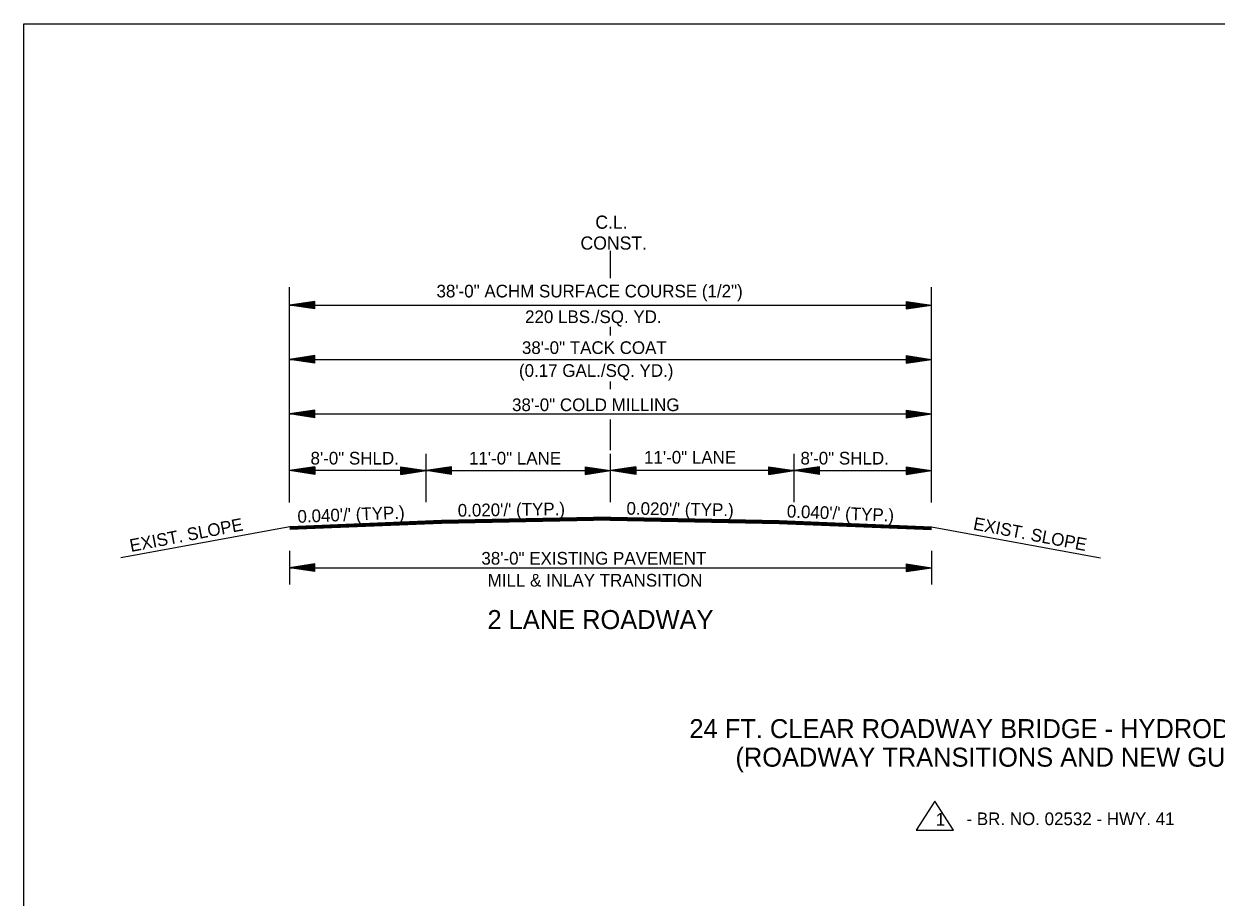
# Model space of a CAD drawing. Extents: x 544199 to 1930787, y -1968972 to 596640.
# Drawn here: x 544199 to 544905, y -1947820 to -1947303 of the extents above; entities that cross this region are included whole.
import ezdxf

# ---------------------------------------------------------------- set-up
doc = ezdxf.new("R2010")
doc.units = 0
for name, color, linetype in [('R_Border', 7, 'Continuous'), ('R_Draft', 7, 'Continuous'), ('R_No Plot', 7, 'Continuous')]:
    doc.layers.add(name, color=color, linetype=linetype)

msp = doc.modelspace()

# ---------------------------------------------------------------- linework, layer by layer
at = {"layer": 'R_Border'}
for p, q in [((544446.09, -1947597.4), (544356.44, -1947600.99)), ((544446.09, -1947597.7), (544356.44, -1947601.29)), ((544446.09, -1947598), (544356.44, -1947601.59)), ((544446.09, -1947598.3), (544356.44, -1947601.89)), ((544446.09, -1947598.6), (544356.44, -1947602.19)), ((544446.09, -1947598.9), (544356.44, -1947602.49)), ((544446.09, -1947599.07), (544356.44, -1947602.66)), ((544646.09, -1947597.4), (544736.09, -1947601)), ((544646.09, -1947597.7), (544736.09, -1947601.3)), ((544646.09, -1947598), (544736.09, -1947601.6)), ((544646.09, -1947598.3), (544736.09, -1947601.9)), ((544646.09, -1947598.6), (544736.09, -1947602.2)), ((544646.09, -1947598.9), (544736.09, -1947602.5)), ((544646.09, -1947599.07), (544736.09, -1947602.67)), ((544738.08, -1947763.37), (544727.04, -1947780.67)), ((544749.12, -1947780.67), (544738.08, -1947763.37)), ((544727.04, -1947780.67), (544749.12, -1947780.67))]:
    msp.add_line(p, q, dxfattribs=at)
at = {"layer": 'R_Draft'}
for p, q in [((544546.09, -1947453.82), (544546.09, -1947437.75)), ((544356.09, -1947586.62), (544356.09, -1947459.14)), ((544736.09, -1947586.62), (544736.09, -1947459.14)), ((544371.09, -1947467.62), (544356.09, -1947469.87)), ((544371.09, -1947468), (544358.59, -1947469.87)), ((544371.09, -1947468.38), (544361.17, -1947469.87)), ((544371.09, -1947468.75), (544363.67, -1947469.87)), ((544371.09, -1947469.14), (544366.21, -1947469.87)), ((544371.09, -1947469.52), (544368.72, -1947469.87)), ((544371.09, -1947472.12), (544371.09, -1947467.62)), ((544721.09, -1947467.62), (544736.09, -1947469.87)), ((544721.09, -1947467.62), (544721.09, -1947472.12)), ((544721.09, -1947468), (544733.58, -1947469.87)), ((544721.09, -1947468.38), (544731, -1947469.87)), ((544721.09, -1947468.75), (544728.51, -1947469.87)), ((544721.09, -1947469.14), (544725.96, -1947469.87)), ((544721.09, -1947469.52), (544723.46, -1947469.87)), ((544356.09, -1947469.87), (544736.09, -1947469.87)), ((544371.09, -1947472.12), (544356.09, -1947469.87)), ((544371.09, -1947471.75), (544358.59, -1947469.87)), ((544371.09, -1947471.36), (544361.17, -1947469.87)), ((544371.09, -1947470.99), (544363.67, -1947469.87)), ((544371.09, -1947470.6), (544366.21, -1947469.87)), ((544371.09, -1947470.22), (544368.72, -1947469.87)), ((544721.09, -1947472.12), (544736.09, -1947469.87)), ((544721.09, -1947470.61), (544725.96, -1947469.87)), ((544721.09, -1947471.36), (544731, -1947469.87)), ((544721.09, -1947471.75), (544733.58, -1947469.87)), ((544721.09, -1947470.99), (544728.51, -1947469.87)), ((544721.09, -1947470.22), (544723.46, -1947469.87)), ((544546.09, -1947487.76), (544546.09, -1947482.72)), ((544371.09, -1947499.77), (544356.09, -1947502.02)), ((544356.09, -1947502.02), (544736.09, -1947502.02)), ((544371.09, -1947504.27), (544356.09, -1947502.02)), ((544371.09, -1947500.14), (544358.59, -1947502.02)), ((544371.09, -1947503.89), (544358.59, -1947502.02)), ((544371.09, -1947500.53), (544361.17, -1947502.02)), ((544371.09, -1947503.51), (544361.17, -1947502.02)), ((544371.09, -1947500.9), (544363.67, -1947502.02)), ((544371.09, -1947503.14), (544363.67, -1947502.02)), ((544371.09, -1947501.28), (544366.21, -1947502.02)), ((544371.09, -1947502.75), (544366.21, -1947502.02)), ((544371.09, -1947501.67), (544368.72, -1947502.02)), ((544371.09, -1947502.37), (544368.72, -1947502.02)), ((544371.09, -1947504.27), (544371.09, -1947499.77)), ((544721.09, -1947499.77), (544736.09, -1947502.02)), ((544721.09, -1947499.77), (544721.09, -1947504.27)), ((544721.09, -1947500.14), (544733.58, -1947502.02)), ((544721.09, -1947500.53), (544731, -1947502.02)), ((544721.09, -1947500.9), (544728.51, -1947502.02)), ((544721.09, -1947501.29), (544725.96, -1947502.02)), ((544721.09, -1947501.67), (544723.46, -1947502.02)), ((544721.09, -1947504.27), (544736.09, -1947502.02)), ((544721.09, -1947502.75), (544725.96, -1947502.02)), ((544721.09, -1947503.51), (544731, -1947502.02)), ((544721.09, -1947503.89), (544733.58, -1947502.02)), ((544721.09, -1947503.14), (544728.51, -1947502.02)), ((544721.09, -1947502.37), (544723.46, -1947502.02)), ((544546.09, -1947519.61), (544546.09, -1947515.15)), ((544371.09, -1947532.01), (544356.09, -1947534.26)), ((544371.09, -1947532.38), (544358.59, -1947534.26)), ((544371.09, -1947532.76), (544361.17, -1947534.26)), ((544371.09, -1947533.14), (544363.67, -1947534.26)), ((544371.09, -1947536.51), (544371.09, -1947532.01)), ((544721.09, -1947532.01), (544736.09, -1947534.26)), ((544721.09, -1947532.01), (544721.09, -1947536.51)), ((544721.09, -1947532.38), (544733.58, -1947534.26)), ((544721.09, -1947532.76), (544731, -1947534.26)), ((544721.09, -1947533.14), (544728.51, -1947534.26)), ((544356.09, -1947534.26), (544736.09, -1947534.26)), ((544371.09, -1947536.51), (544356.09, -1947534.26)), ((544371.09, -1947536.13), (544358.59, -1947534.26)), ((544371.09, -1947535.75), (544361.17, -1947534.26)), ((544371.09, -1947535.37), (544363.67, -1947534.26)), ((544371.09, -1947533.52), (544366.21, -1947534.26)), ((544371.09, -1947534.98), (544366.21, -1947534.26)), ((544371.09, -1947533.9), (544368.72, -1947534.26)), ((544371.09, -1947534.61), (544368.72, -1947534.26)), ((544546.09, -1947555.78), (544546.09, -1947537.59)), ((544721.09, -1947533.53), (544725.96, -1947534.26)), ((544721.09, -1947533.9), (544723.46, -1947534.26)), ((544721.09, -1947536.51), (544736.09, -1947534.26)), ((544721.09, -1947534.99), (544725.96, -1947534.26)), ((544721.09, -1947535.75), (544731, -1947534.26)), ((544721.09, -1947536.13), (544733.58, -1947534.26)), ((544721.09, -1947535.37), (544728.51, -1947534.26)), ((544721.09, -1947534.61), (544723.46, -1947534.26)), ((544437.1, -1947586.45), (544437.1, -1947557.9)), ((544546.09, -1947586.45), (544546.09, -1947557.9)), ((544654.85, -1947586.45), (544654.85, -1947557.9)), ((544371.09, -1947565.54), (544356.09, -1947567.79)), ((544437.1, -1947567.79), (544356.09, -1947567.79)), ((544371.09, -1947570.04), (544356.09, -1947567.79)), ((544371.09, -1947565.92), (544358.59, -1947567.79)), ((544371.09, -1947569.67), (544358.59, -1947567.79)), ((544371.09, -1947566.3), (544361.17, -1947567.79)), ((544371.09, -1947569.29), (544361.17, -1947567.79)), ((544371.09, -1947566.68), (544363.67, -1947567.79)), ((544371.09, -1947568.91), (544363.67, -1947567.79)), ((544371.09, -1947567.07), (544366.21, -1947567.79)), ((544371.09, -1947568.53), (544366.21, -1947567.79)), ((544371.09, -1947567.44), (544368.72, -1947567.79)), ((544371.09, -1947568.15), (544368.72, -1947567.79)), ((544371.09, -1947565.54), (544371.09, -1947570.04)), ((544422.1, -1947565.54), (544437.1, -1947567.79)), ((544422.1, -1947570.04), (544422.1, -1947565.54)), ((544422.1, -1947565.92), (544434.59, -1947567.79)), ((544422.1, -1947566.3), (544432.01, -1947567.79)), ((544422.1, -1947566.68), (544429.52, -1947567.79)), ((544422.1, -1947567.06), (544426.97, -1947567.79)), ((544422.1, -1947567.44), (544424.47, -1947567.79)), ((544422.1, -1947570.04), (544437.1, -1947567.79)), ((544422.1, -1947568.52), (544426.97, -1947567.79)), ((544422.1, -1947569.29), (544432.01, -1947567.79)), ((544422.1, -1947569.67), (544434.59, -1947567.79)), ((544422.1, -1947568.91), (544429.52, -1947567.79)), ((544422.1, -1947568.15), (544424.47, -1947567.79)), ((544452.1, -1947565.54), (544437.1, -1947567.79)), ((544452.1, -1947570.04), (544437.1, -1947567.79)), ((544437.1, -1947567.79), (544546.09, -1947567.79)), ((544452.1, -1947565.92), (544439.6, -1947567.79)), ((544452.1, -1947569.67), (544439.6, -1947567.79)), ((544452.1, -1947566.3), (544442.18, -1947567.79)), ((544452.1, -1947569.29), (544442.18, -1947567.79)), ((544452.1, -1947566.68), (544444.68, -1947567.79)), ((544452.1, -1947568.91), (544444.68, -1947567.79)), ((544452.1, -1947567.06), (544447.22, -1947567.79)), ((544452.1, -1947568.52), (544447.22, -1947567.79)), ((544452.1, -1947567.44), (544449.73, -1947567.79)), ((544452.1, -1947568.15), (544449.73, -1947567.79)), ((544452.1, -1947570.04), (544452.1, -1947565.54)), ((544531.09, -1947565.54), (544546.09, -1947567.79)), ((544531.09, -1947565.54), (544531.09, -1947570.04)), ((544531.09, -1947565.92), (544543.58, -1947567.79)), ((544531.09, -1947566.3), (544541, -1947567.79)), ((544531.09, -1947566.68), (544538.51, -1947567.79)), ((544531.09, -1947567.07), (544535.96, -1947567.79)), ((544531.09, -1947567.44), (544533.46, -1947567.79)), ((544531.09, -1947570.04), (544546.09, -1947567.79)), ((544531.09, -1947568.53), (544535.96, -1947567.79)), ((544531.09, -1947569.29), (544541, -1947567.79)), ((544531.09, -1947569.67), (544543.58, -1947567.79)), ((544531.09, -1947568.91), (544538.51, -1947567.79)), ((544531.09, -1947568.15), (544533.46, -1947567.79)), ((544561.09, -1947565.54), (544546.09, -1947567.79)), ((544654.85, -1947567.79), (544546.09, -1947567.79)), ((544561.09, -1947570.04), (544546.09, -1947567.79)), ((544561.09, -1947565.92), (544548.59, -1947567.79)), ((544561.09, -1947569.67), (544548.59, -1947567.79)), ((544561.09, -1947566.3), (544551.17, -1947567.79)), ((544561.09, -1947569.29), (544551.17, -1947567.79)), ((544561.09, -1947566.68), (544553.67, -1947567.79)), ((544561.09, -1947568.91), (544553.67, -1947567.79)), ((544561.09, -1947567.07), (544556.21, -1947567.79)), ((544561.09, -1947568.53), (544556.21, -1947567.79)), ((544561.09, -1947567.44), (544558.72, -1947567.79)), ((544561.09, -1947568.15), (544558.72, -1947567.79)), ((544561.09, -1947565.54), (544561.09, -1947570.04)), ((544639.85, -1947565.54), (544654.85, -1947567.79)), ((544639.85, -1947570.04), (544639.85, -1947565.54)), ((544639.85, -1947565.92), (544652.34, -1947567.79)), ((544639.85, -1947566.3), (544649.76, -1947567.79)), ((544639.85, -1947566.68), (544647.26, -1947567.79)), ((544639.85, -1947567.06), (544644.72, -1947567.79)), ((544639.85, -1947567.44), (544642.22, -1947567.79)), ((544639.85, -1947570.04), (544654.85, -1947567.79)), ((544639.85, -1947568.52), (544644.72, -1947567.79)), ((544639.85, -1947569.29), (544649.76, -1947567.79)), ((544639.85, -1947569.67), (544652.34, -1947567.79)), ((544639.85, -1947568.91), (544647.26, -1947567.79)), ((544639.85, -1947568.15), (544642.22, -1947567.79)), ((544669.85, -1947565.54), (544654.85, -1947567.79)), ((544654.85, -1947567.79), (544736.09, -1947567.79)), ((544669.85, -1947570.04), (544654.85, -1947567.79)), ((544669.85, -1947565.92), (544657.35, -1947567.79)), ((544669.85, -1947569.67), (544657.35, -1947567.79)), ((544669.85, -1947566.3), (544659.93, -1947567.79)), ((544669.85, -1947569.29), (544659.93, -1947567.79)), ((544669.85, -1947566.68), (544662.43, -1947567.79)), ((544669.85, -1947568.91), (544662.43, -1947567.79)), ((544669.85, -1947567.06), (544664.97, -1947567.79)), ((544669.85, -1947568.52), (544664.97, -1947567.79)), ((544669.85, -1947567.44), (544667.48, -1947567.79)), ((544669.85, -1947568.15), (544667.48, -1947567.79)), ((544669.85, -1947570.04), (544669.85, -1947565.54)), ((544721.09, -1947565.54), (544736.09, -1947567.79)), ((544721.09, -1947565.54), (544721.09, -1947570.04)), ((544721.09, -1947565.92), (544733.58, -1947567.79)), ((544721.09, -1947566.3), (544731, -1947567.79)), ((544721.09, -1947566.68), (544728.51, -1947567.79)), ((544721.09, -1947567.07), (544725.96, -1947567.79)), ((544721.09, -1947567.44), (544723.46, -1947567.79)), ((544721.09, -1947570.04), (544736.09, -1947567.79)), ((544721.09, -1947568.53), (544725.96, -1947567.79)), ((544721.09, -1947569.29), (544731, -1947567.79)), ((544721.09, -1947569.67), (544733.58, -1947567.79)), ((544721.09, -1947568.91), (544728.51, -1947567.79)), ((544721.09, -1947568.15), (544723.46, -1947567.79)), ((544546.09, -1947595.4), (544446.09, -1947597.4)), ((544546.08, -1947595.7), (544446.09, -1947597.7)), ((544546.09, -1947596), (544446.09, -1947598)), ((544546.11, -1947596.3), (544446.09, -1947598.3)), ((544546.11, -1947596.6), (544446.09, -1947598.6)), ((544546.07, -1947596.3), (544646.09, -1947598.3)), ((544546.07, -1947596.6), (544646.09, -1947598.6)), ((544546.08, -1947595.7), (544646.09, -1947597.7)), ((544546.08, -1947596), (544646.09, -1947598)), ((544546.09, -1947595.4), (544646.09, -1947597.4)), ((544356.44, -1947600.99), (544256.37, -1947619.36)), ((544546.12, -1947596.9), (544446.09, -1947598.9)), ((544546.12, -1947597.07), (544446.09, -1947599.07)), ((544546.06, -1947596.9), (544646.09, -1947598.9)), ((544546.06, -1947597.07), (544646.09, -1947599.07)), ((544736.09, -1947601), (544836.16, -1947619.38)), ((544356.09, -1947615.26), (544356.09, -1947635.26)), ((544736.09, -1947615.26), (544736.09, -1947635.26)), ((544371.09, -1947623.01), (544356.09, -1947625.26)), ((544371.09, -1947623.38), (544358.59, -1947625.26)), ((544371.09, -1947623.77), (544361.17, -1947625.26)), ((544371.09, -1947624.14), (544363.67, -1947625.26)), ((544371.09, -1947624.52), (544366.21, -1947625.26)), ((544371.09, -1947624.91), (544368.72, -1947625.26)), ((544371.09, -1947627.51), (544371.09, -1947623.01)), ((544721.09, -1947623.01), (544736.09, -1947625.26)), ((544721.09, -1947623.01), (544721.09, -1947627.51)), ((544721.09, -1947623.38), (544733.58, -1947625.26)), ((544721.09, -1947623.77), (544731, -1947625.26)), ((544721.09, -1947624.14), (544728.51, -1947625.26)), ((544721.09, -1947624.53), (544725.96, -1947625.26)), ((544721.09, -1947624.91), (544723.46, -1947625.26)), ((544356.09, -1947625.26), (544736.09, -1947625.26)), ((544371.09, -1947627.51), (544356.09, -1947625.26)), ((544371.09, -1947627.13), (544358.59, -1947625.26)), ((544371.09, -1947626.75), (544361.17, -1947625.26)), ((544371.09, -1947626.38), (544363.67, -1947625.26)), ((544371.09, -1947625.99), (544366.21, -1947625.26)), ((544371.09, -1947625.61), (544368.72, -1947625.26)), ((544721.09, -1947627.51), (544736.09, -1947625.26)), ((544721.09, -1947625.99), (544725.96, -1947625.26)), ((544721.09, -1947626.75), (544731, -1947625.26)), ((544721.09, -1947627.13), (544733.58, -1947625.26)), ((544721.09, -1947626.38), (544728.51, -1947625.26)), ((544721.09, -1947625.61), (544723.46, -1947625.26))]:
    msp.add_line(p, q, dxfattribs=at)
at = {"layer": 'R_No Plot'}
msp.add_lwpolyline([(544198.93, -1947831.01), (544198.93, -1947303.39), (545382.98, -1947303.39), (545382.98, -1947352.79), (545560.58, -1947352.79), (545560.58, -1947370.64), (545578.78, -1947370.64), (545578.78, -1947367.39), (545656.45, -1947367.39)], dxfattribs=at)

# ---------------------------------------------------------------- texts
at = {"layer": 'R_Draft'}
for s, height, p in [('C.L.', 7.8, (544537.19, -1947424.66)), ('CONST.', 7.8, (544528.41, -1947437.02)), ('38\'-0" ACHM SURFACE COURSE (1/2")', 7.5, (544443.19, -1947465.3)), ('220 LBS./SQ. YD. ', 7.5, (544495.6, -1947480.48)), ('38\'-0" TACK COAT', 7.5, (544493.74, -1947498.77)), ('(0.17 GAL./SQ. YD.)', 7.5, (544492, -1947512.31)), ('38\'-0" COLD MILLING', 7.5, (544487.89, -1947532.59)), ('8\'-0" SHLD.', 7.5, (544368.61, -1947564.19)), ('11\'-0" LANE', 7.5, (544462.41, -1947564.19)), ('11\'-0" LANE', 7.5, (544566.03, -1947563.66)), ('8\'-0" SHLD.', 7.5, (544658.61, -1947564.19)), ('38\'-0" EXISTING PAVEMENT', 7.5, (544469.76, -1947623.43)), ('MILL & INLAY TRANSITION', 7.5, (544473.48, -1947636.43)), ('2 LANE ROADWAY', 11.25, (544473.36, -1947661.58)), ('24 FT. CLEAR ROADWAY BRIDGE - HYDRODEMOLITION', 11.25, (544592.89, -1947726.13)), ('(ROADWAY TRANSITIONS AND NEW GUARDRAIL)', 11.25, (544620.13, -1947743.01)), ('1', 7.5, (544738.69, -1947777.94)), ('- BR. NO. 02532 - HWY. 41', 7.5, (544756.88, -1947777.62))]:
    msp.add_text(s, height=height, dxfattribs=at).set_placement(p)
for s, rotation, p in [("0.040'/' (TYP.)", 2.29061, (544361.03, -1947598.73)), ("0.020'/' (TYP.)", 0.87191, (544455.81, -1947595.08)), ("0.020'/' (TYP.)", 359.12809, (544555.59, -1947593.85)), ("0.040'/' (TYP.)", 357.70939, (544650.43, -1947595.5)), ('EXIST. SLOPE', 10.88286, (544262.35, -1947615.98)), ('EXIST. SLOPE', 349.11714, (544760.47, -1947602.6))]:
    msp.add_text(s, height=7.5, rotation=rotation, dxfattribs=at).set_placement(p)

doc.saveas('drawing.dxf')
